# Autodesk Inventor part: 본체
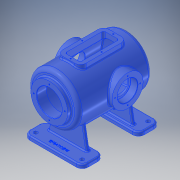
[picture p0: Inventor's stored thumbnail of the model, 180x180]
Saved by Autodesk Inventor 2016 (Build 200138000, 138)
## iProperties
Created: 2016-02
Part Number: 본체
Material: 알루미늄 6061
Document SubType Name: Modeling
Designer: mduedu
Density: 2.71 g/cm^3
Mass: 3305.58 g
Surface Area: 2487 cm^2
Volume: 1219.77 cm^3
Appearance: 알루미늄 - 평지
Author: mduedu
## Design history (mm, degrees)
sketch "스케치2"
  geometry: L1 (0, 100)-(0, -100); L2 (65, -87.083)-(65, 100); L3 (65, 100)-(0, 100); A1 r 170 centre (0, 70) between (0, -100) and (65, -87.083); 2 further points
  constraints: 6 end point, 2 point on circle, 1 centre point, 1 coincident, 1 horizontal, 1 midpoint, 1 parallel, 1 point on line, 1 vertical
  dimensions: "d3" = 200 distance of L1.start L1.end; "d5" = 130 diameter of L2 L1; "d6" = 170 radius of A1
revolve "회전1" sketch "스케치2" stored, may be unused: angle "d7" = 90 deg
sketch "스케치3"
  geometry: C1 r 47.5 at (0, 0); 1 further point
  constraints: 1 centre point, 1 coincident
  dimensions: "d8" = 95 diameter of C1
extrude "돌출2" join sketch "스케치3" distance "d10" = 10; taper "d11" = 0 deg
sketch "스케치5"
  geometry: L1 (47.5, 110)-(47.5, 100) reference; L2 (47.5, 100)-(65, 100) reference; L3 (65, 100)-(65, -87.083) reference; L4 (-65, -87.083)-(-65, 100) reference; L5 (-65, 100)-(-47.5, 100) reference; L6 (-47.5, 100)-(-47.5, 110) reference; L7 (-47.5, 110)-(47.5, 110) reference; L8 (55, 85)-(55, -80.25); L9 (0, 85)-(55, 85); L10 (0, 85)-(0, -90); A1 r 170 centre (0, 70) between (-65, -87.083) and (0, -100) reference; A2 r 170 centre (0, 70) between (0, -100) and (65, -87.083) reference; A3 r 160 centre (0, 70) between (0, -90) and (55, -80.25); 1 further point
  constraints: 6 end point, 2 point on circle, 1 centre point, 1 parallel, 1 perpendicular, 1 point on line, 1 vertical
  dimensions: "d13" = 10 distance between parallel lines of L3 L8; "d14" = 10 radial gap between concentric circles of A3 A1; "d15" = 15 distance between parallel lines of L9 L2
revolve "회전2" sketch "스케치5" stored, may be unused: angle "d16" = 90 deg
hole "구멍1" diameter "d19" = 65; stored, may be unused: countersink angle "d23" = 90 deg, drill point angle "d25" = 118 deg; dims "d17" = 10, "d18" = 10, "d20" = 6, "d21" = 4, "d22" = 2, "d24" = 8
node "작업 평면1"
sketch "스케치6"
  geometry: L1 (47.5, 110)-(-47.5, 110) reference; C1 r 40 at (0, -17); 1 further point
  constraints: 1 centre point, 1 vertical alignment
  dimensions: "d27" = 80 diameter of C1; "d29" = 127 distance from line of C1.centre L1
extrude "돌출3" join sketch "스케치6" stored distance "d30" = 10; taper "d31" = 0 deg
hole "구멍2" diameter "d34" = 42; stored, may be unused: countersink angle "d38" = 90 deg, drill point angle "d40" = 118 deg; dims "d32" = 10, "d33" = 10, "d35" = 6, "d36" = 52, "d37" = 18, "d39" = 8
sketch "스케치7" dims "d41" = 65
  geometry: C1 r 40 at (0, 0) reference; 3 further points
  constraints: 2 vertical alignment, 1 coincident, 2 other
hole "구멍3" sketch "스케치7" at (0, 32.5) diameter "d43" = 3.242; stored, may be unused: countersink angle "d47" = 90 deg, drill point angle "d49" = 118 deg; dims "d44" = 11, "d45" = 13, "d46" = 18, "d48" = 13
sketch "스케치8" dims "d53" = 80
  geometry: 3 further points
  constraints: 2 vertical alignment, 1 coincident, 2 other
hole "구멍4" sketch "스케치8" at (0, 40) diameter "d56" = 3.242; stored, may be unused: countersink angle "d60" = 90 deg, drill point angle "d62" = 118 deg; dims "d57" = 11, "d58" = 13, "d59" = 18, "d61" = 13
fillet "모깎기1" dims "d66" = 10
fillet "모깎기2" dims "d67" = 3
fillet "모깎기3" dims "d68" = 0.3
chamfer "모따기1" distance "d69" = 1; stored, may be unused: second distance "d70" = 2, angle "d71" = 45 deg
node "작업 평면2"
sketch "스케치9"
  geometry: L1 (75, 100)-(-75, 100); L2 (-75, 100)-(-75, -100); L3 (-75, -100)-(75, -100); L4 (75, -100)-(75, 100); 1 further point
  constraints: 8 end point, 2 parallel, 1 horizontal, 1 perpendicular
  dimensions: "d73" = 200 distance of L3.end L1.start; "d75" = 150 distance of L2.end L3.end; "d76" = 100 distance from line of L1 point (0, 0); "d77" = 75 distance from line of L4 point (0, 0)
extrude "돌출4" join sketch "스케치9" distance "d78" = 10; taper "d79" = 0 deg
sketch "스케치10"
  geometry: L1 (-75, -100)-(75, -100) reference; L2 (75, 100)-(-75, 100) reference; L3 (0, -100)-(0, 100); L4 (-75, 100)-(-75, -100) reference; L5 (75, -100)-(75, 100) reference; L6 (-75, 0)-(75, 0); L7 (-50, -63)-(50, -63); L8 (50, -63)-(50, -55); L9 (50, -55)-(-50, -55); L10 (-50, -55)-(-50, -63); L11 (-50, 63)-(50, 63); L12 (50, 63)-(50, 55); L13 (50, 55)-(-50, 55); L14 (-50, 55)-(-50, 63); 1 further point
  constraints: 20 end point, 4 midpoint, 4 symmetric about line, 2 parallel, 1 horizontal, 1 perpendicular, 1 other
  dimensions: "d80" = 8 distance of L9.end L7.start; "d82" = 100 distance of L7.start L7.end; "d83" = 55 distance between parallel lines of L9 L6
extrude "돌출5" join sketch "스케치10" stored distance "d84" = 10; taper "d85" = 0 deg
feature "면 기울기1" dims angle "d86" = 10 deg
sketch "스케치11"
  geometry: L1 (-110, 55)-(-51.482, 55) reference; L2 (-110, -55)-(-51.482, -55) reference; L3 (-95, 55)-(-95, -55); L4 (-65, 90)-(-65, -80.25) reference; 1 further point
  constraints: 2 end point, 2 point on line, 1 perpendicular
  dimensions: "d87" = 30 distance between parallel lines of L3 L4
feature "리브1" sketch "스케치11" dims "d88" = 1, "d89" = 8, "d90" = 0, "d91" = 0, "d92" = 1, "d93" = 1
sketch "스케치12"
  geometry: L1 (-110, 55)-(-51.482, 55) reference; L2 (-110, -55)-(-51.482, -55) reference; L3 (-110, 100)-(-110, -100) reference; L4 (-120, 152)-(-120, -142) reference; L5 (-110, 45)-(-120, 45); L6 (-120, 45)-(-120, -45); L7 (-120, -45)-(-110, -45); L8 (-110, -45)-(-110, 45); 1 further point
  constraints: 8 end point, 2 parallel, 2 point on line, 1 horizontal, 1 perpendicular
  dimensions: "d94" = 10 distance between parallel lines of L7 L2; "d95" = 10 distance between parallel lines of L1 L5
extrude "돌출6" cut sketch "스케치12" stored distance "d96" = 10; taper "d97" = 0 deg
fillet "모깎기4" dims "d98" = 15
sketch "스케치13"
  geometry: C1 r 5 at (-60, -85); C2 r 5 at (60, -85); C3 r 5 at (60, 85); C4 r 5 at (-60, 85); A1 r 15 centre (-60, -85) between (-75, -85) and (-60, -100) reference; A2 r 15 centre (60, -85) between (60, -100) and (75, -85) reference; A3 r 15 centre (60, 85) between (75, 85) and (60, 100) reference; A4 r 15 centre (-60, 85) between (-60, 100) and (-75, 85) reference; 1 further point
  constraints: 4 centre point, 4 coincident, 3 equal radius
  dimensions: "d99" = 10 diameter of C1
extrude "돌출7" cut sketch "스케치13" stored distance "d101" = 10; taper "d102" = 0 deg
fillet "모깎기5" dims "d103" = 3, "d104" = 3
fillet "모깎기6" dims "d105" = 3
sketch "스케치14"
  geometry: L1 (-60, -100)-(60, -100) reference; 2 further points
  constraints: 1 vertical alignment, 1 other
  dimensions: "d106" = 15 distance from line of point (0, -85) L1
feature "엠보싱1" sketch "스케치14" dims "d3" = 200, "d5" = 130, "d6" = 170, "d14" = 10, "d107" = 0.5, "d108" = 0
node "작업 평면3"
sketch "스케치15"
  geometry: L1 (-30, 60)-(30, 60); L2 (30, 60)-(30, -60); L3 (30, -60)-(-30, -60); L4 (-30, -60)-(-30, 60); 2 further points
  constraints: 8 end point, 2 parallel, 1 horizontal, 1 midpoint, 1 perpendicular, 1 vertical alignment
  dimensions: "d110" = 60 distance of L2.end L3.end; "d112" = 60 distance from line of L3 point (0, 0); "d113" = 120 distance of L1.end L2.end
extrude "돌출8" join sketch "스케치15" stored distance "d114" = 10; taper "d115" = 0 deg
fillet "모깎기7" dims "d116" = 15
sketch "스케치16"
  geometry: L1 (-30, -45)-(-30, 45) reference; L2 (-15, 60)-(15, 60) reference; L3 (30, 45)-(30, -45) reference; L4 (15, -60)-(-15, -60) reference; L5 (15, 50)-(-15, 50); L6 (-20, 45)-(-20, -45); L7 (-15, -50)-(15, -50); L8 (20, -45)-(20, 45); A1 r 15 centre (-15, -45) between (-30, -45) and (-15, -60) reference; A2 r 15 centre (-15, 45) between (-15, 60) and (-30, 45) reference; A3 r 15 centre (15, 45) between (30, 45) and (15, 60) reference; A4 r 15 centre (15, -45) between (15, -60) and (30, -45) reference; A5 r 5 centre (-15, 45) between (-15, 50) and (-20, 45); A6 r 5 centre (-15, -45) between (-20, -45) and (-15, -50); A7 r 5 centre (15, -45) between (15, -50) and (20, -45); A8 r 5 centre (15, 45) between (20, 45) and (15, 50); 1 further point
  constraints: 8 end point, 8 point on circle, 4 centre point, 7 other
  dimensions: "d117" = 10 distance between parallel lines of L6 L1
extrude "돌출9" cut sketch "스케치16" stored distance "d118" = 10; taper "d119" = 0 deg
fillet "모깎기8" dims "d120" = 3
sketch "스케치17"
  geometry: L1 (-30, -45)-(-30, 45) reference; L2 (-15, 60)-(15, 60) reference; L3 (30, 45)-(30, -45) reference; L4 (15, -60)-(-15, -60) reference; L5 (20, -45)-(20, 45) reference; L6 (15, 50)-(-15, 50) reference; L7 (-20, 45)-(-20, -45) reference; L8 (-15, -50)-(15, -50) reference; L9 (15, 55)-(-15, 55); L10 (-25, 45)-(-25, -45); L11 (-15, -55)-(15, -55); L12 (25, -45)-(25, 45); A1 r 15 centre (-15, 45) between (-15, 60) and (-30, 45) reference; A2 r 15 centre (15, 45) between (30, 45) and (15, 60) reference; A3 r 15 centre (15, -45) between (15, -60) and (30, -45) reference; A4 r 15 centre (-15, -45) between (-30, -45) and (-15, -60) reference; A5 r 5 centre (15, -45) between (15, -50) and (20, -45) reference; A6 r 5 centre (15, 45) between (20, 45) and (15, 50) reference; A7 r 5 centre (-15, 45) between (-15, 50) and (-20, 45) reference; A8 r 5 centre (-15, -45) between (-20, -45) and (-15, -50) reference; A9 r 10 centre (-15, 45) between (-15, 55) and (-25, 45); A10 r 10 centre (-15, -45) between (-25, -45) and (-15, -55); A11 r 10 centre (15, -45) between (15, -55) and (25, -45); A12 r 10 centre (15, 45) between (25, 45) and (15, 55); 5 further points
  constraints: 8 end point, 8 point on circle, 4 centre point, 4 midpoint, 7 other
  dimensions: "d121" = 5 distance between parallel lines of L10 L1
hole "구멍5" sketch "스케치17" at (0, 55), (25, 0), (0, -55), (-25, 0) diameter "d122" = 3.242; stored, may be unused: countersink angle "d126" = 90 deg, drill point angle "d128" = 118 deg; dims "d123" = 9, "d124" = 13, "d125" = 18, "d127" = 11
fillet "모깎기9" dims "d129" = 3
node "솔리드2"
pattern_circular "원형 패턴1" dims angle "d51" = 360 deg
mirror "대칭1"
pattern_circular "원형 패턴2" dims angle "d64" = 360 deg
node "절단 모서리 투영1"
node "절단 모서리 투영2"
node "절단 모서리 투영3"
other parameters: "d26" = 75
